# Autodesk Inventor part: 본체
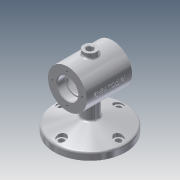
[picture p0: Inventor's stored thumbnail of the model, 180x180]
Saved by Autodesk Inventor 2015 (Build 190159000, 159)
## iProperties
Created: 2018-12
Part Number: 본체
Material: 알루미늄 6061
Document SubType Name: Modeling
Designer: now
Density: 2.7 g/cm^3
Appearance: 알루미늄 - 평지
Mass: 684.769 g
Surface Area: 556.949 cm^2
Volume: 253.618 cm^3
Author: now
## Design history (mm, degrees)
sketch "스케치1"
  geometry: C1 r 30 at (0, 0); 1 further point
  constraints: 1 centre point, 1 coincident
  dimensions: "d0" = 60 diameter of C1
extrude "돌출1" new body sketch "스케치1" stored distance "d1" = 70; taper "d2" = 0 deg
sketch "스케치2"
  geometry: L1 (-35, -30)-(-35, 30) reference; L2 (-35, 30)-(35, 30) reference; L3 (35, 30)-(35, -30) reference; L4 (35, -30)-(-35, -30) reference; L5 (-35, 0)-(-23, 0); L6 (-23, 0)-(-23, 15.7); L7 (-23.3, 16)-(-35, 16); L8 (-35, 16)-(-35, 0); L9 (-23, 0)-(-20, 0); L10 (-20, 0)-(-20, 14); L11 (-20, 14)-(-23, 14); L12 (-23, 14)-(-23, 0); L13 (-20, 0)-(20, 0); L14 (20, 0)-(20, 22); L15 (17, 25)-(-17, 25); L16 (-20, 22)-(-20, 0); L17 (20, 0)-(23, 0); L18 (23, 0)-(23, 14); L19 (23, 14)-(20, 14); L20 (20, 14)-(20, 0); L21 (35, -30)-(35, 30) reference; L22 (23, 0)-(35, 0); L23 (35, 0)-(35, 16); L24 (35, 16)-(23.3, 16); L25 (23, 15.7)-(23, 0); A1 r 3 centre (-17, 22) between (-17, 25) and (-20, 22); A2 r 3 centre (17, 22) between (20, 22) and (17, 25); A3 r 0.3 centre (-23.3, 15.7) between (-23, 15.7) and (-23.3, 16); A4 r 0.3 centre (23.3, 15.7) between (23.3, 16) and (23, 15.7); 1 further point
  constraints: 40 end point, 10 parallel, 8 point on circle, 8 tangent, 5 horizontal, 5 perpendicular, 4 centre point, 2 equal radius, 1 midpoint, 1 point on line
  dimensions: "d3" = 16 distance between parallel lines of L5 L7; "d4" = 12 distance between parallel lines of L1 L6; "d5" = 14 distance between parallel lines of L9 L11; "d6" = 40 distance between parallel lines of L14 L16; "d7" = 25 distance between parallel lines of L13 L15; "d8" = 3 distance between parallel lines of L10 L12; "d9" = 3 distance between parallel lines of L20 L18; "d10" = 14 distance between parallel lines of L19 L17; "d11" = 16 distance between parallel lines of L22 L24; "d12" = 3 radius of A1; "d13" = 0.3 radius of A3
revolve "회전1" sketch "스케치2" stored, may be unused: angle "d14" = 90 deg
chamfer "모따기1" distance "d15" = 1; stored, may be unused: second distance "d16" = 2, angle "d17" = 45 deg
sketch "스케치3" dims "d18" = 46
  geometry: C1 r 30 at (0, 0) reference; C2 r 17 at (0, 0) reference; 2 further points
  constraints: 2 vertical alignment, 1 coincident, 2 other
hole "구멍1" sketch "스케치3" at (0, 23) diameter "d19" = 3.242; stored, may be unused: countersink angle "d23" = 90 deg, drill point angle "d25" = 118 deg; dims "d20" = 8, "d21" = 4, "d22" = 2, "d24" = 10
node "작업 평면1"
sketch "스케치4"
  geometry: C1 r 55 at (0, 0); 1 further point
  constraints: 1 centre point, 1 coincident
  dimensions: "d30" = 110 diameter of C1
extrude "돌출2" join sketch "스케치4" distance "d31" = 11; taper "d32" = 0 deg
sketch "스케치5"
  geometry: C1 r 55 at (0, 0) reference; C2 r 12 at (0, 0)
  constraints: 1 centre point, 1 coincident
  dimensions: "d33" = 24 diameter of C2
extrude "돌출3" join sketch "스케치5" stored distance "d34" = 10; taper "d35" = 0 deg
node "작업 평면2"
sketch "스케치6"
  geometry: C1 r 10 at (0, 0); 1 further point
  constraints: 1 centre point, 1 coincident
  dimensions: "d37" = 20 diameter of C1
extrude "돌출4" join sketch "스케치6" stored distance "d38" = 10; taper "d39" = 0 deg
sketch "스케치7"
  geometry: C1 r 10 at (0, 0) reference; C2 r 5 at (0, 0)
  constraints: 1 centre point, 1 coincident
  dimensions: "d40" = 10 diameter of C2
extrude "돌출5" cut sketch "스케치7" stored distance "d41" = 10; taper "d42" = 0 deg
chamfer "모따기2" distance "d43" = 1; stored, may be unused: second distance "d44" = 2, angle "d45" = 45 deg
fillet "모깎기1" dims "d46" = 3
fillet "모깎기2" dims "d47" = 3
node "작업 평면3"
sketch "스케치8"
  geometry: L1 (-10, 37)-(10, 37) reference; L2 (-35, 30)-(-35, -30) reference; L3 (39.999, -75)-(-39.999, -75) reference; L4 (-39.999, -75)-(-39.999, -64) reference; L5 (-39.999, -64)-(39.999, -64) reference; L6 (39.999, -64)-(39.999, -75) reference; 2 further points
  constraints: 1 other
  dimensions: "d52" = 0 distance of point (0, 0) point (0, 0)
feature "엠보싱1" sketch "스케치8" dims "d3" = 16, "d4" = 12, "d5" = 14, "d6" = 40, "d7" = 25, "d8" = 3, "d9" = 3, "d10" = 14, "d11" = 16, "d12" = 3, "d13" = 0.3, "d53" = 0.5, "d54" = 0
sketch "스케치9"
  geometry: L1 (-23, 14)-(-23, 15.7) reference; L2 (-23.3, 16)-(-34, 16) reference; L3 (-34, 16)-(-35, 17) reference; L4 (-35, 17)-(-35, 21.379) reference; L5 (-35, 21.379)-(-25, 21.379) reference; L6 (-25, 21.379)-(-24.026, 23) reference; L7 (-24.026, 23)-(-25, 24.621) reference; L8 (-25, 24.621)-(-35, 24.621) reference; L9 (-35, 24.621)-(-35, 30) reference; L10 (-35, 30)-(-13, 30) reference; L11 (-10, 33)-(-10, 37) reference; L12 (-10, 37)-(-6, 37) reference; L13 (-6, 37)-(-5, 36) reference; L14 (-5, 36)-(-5, 25) reference; L15 (-5, 25)-(-17, 25) reference; L16 (-20, 22)-(-20, 14) reference; L17 (-20, 14)-(-23, 14) reference; L18 (23, 15.7)-(23, 14) reference; L19 (23, 14)-(20, 14) reference; L20 (20, 14)-(20, 22) reference; L21 (17, 25)-(5, 25) reference; L22 (5, 25)-(5, 36) reference; L23 (5, 36)-(6, 37) reference; L24 (6, 37)-(10, 37) reference; L25 (10, 37)-(10, 33) reference; L26 (13, 30)-(35, 30) reference; L27 (35, 30)-(35, 24.621) reference; L28 (35, 24.621)-(25, 24.621) reference; L29 (25, 24.621)-(24.026, 23) reference; L30 (24.026, 23)-(25, 21.379) reference; L31 (25, 21.379)-(35, 21.379) reference; L32 (35, 21.379)-(35, 17) reference; L33 (35, 17)-(34, 16) reference; L34 (34, 16)-(23.3, 16) reference; L35 (23, -14)-(23, -15.7) reference; L36 (23.3, -16)-(34, -16) reference; L37 (34, -16)-(35, -17) reference; L38 (35, -17)-(35, -21.379) reference; L39 (35, -21.379)-(25, -21.379) reference; L40 (25, -21.379)-(24.026, -23) reference; L41 (24.026, -23)-(25, -24.621) reference; L42 (25, -24.621)-(35, -24.621) reference; L43 (35, -24.621)-(35, -30) reference; L44 (35, -30)-(15, -30) reference; L45 (12, -33)-(12, -64) reference; L46 (12, -64)-(55, -64) reference; L47 (55, -64)-(55, -75) reference; L48 (55, -75)-(-55, -75) reference; L49 (-55, -75)-(-55, -64) reference; L50 (-55, -64)-(-12, -64) reference; L51 (-12, -64)-(-12, -33) reference; L52 (-15, -30)-(-35, -30) reference; L53 (-35, -30)-(-35, -24.621) reference; L54 (-35, -24.621)-(-25, -24.621) reference; L55 (-25, -24.621)-(-24.026, -23) reference; L56 (-24.026, -23)-(-25, -21.379) reference; L57 (-25, -21.379)-(-35, -21.379) reference; L58 (-35, -21.379)-(-35, -17) reference; L59 (-35, -17)-(-34, -16) reference; L60 (-34, -16)-(-23.3, -16) reference; L61 (-23, -15.7)-(-23, -14) reference; L62 (-23, -14)-(-20, -14) reference; L63 (-20, -14)-(-20, -22) reference; L64 (-17, -25)-(17, -25) reference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; A1 r 0.3 centre (-23.3, 15.7) between (-23, 15.7) and (-23.3, 16) reference; A2 r 3 centre (-17, 22) between (-17, 25) and (-20, 22) reference; A3 r 3 centre (17, 22) between (20, 22) and (17, 25) reference; A4 r 0.3 centre (23.3, 15.7) between (23.3, 16) and (23, 15.7) reference; A5 r 0.3 centre (23.3, -15.7) between (23, -15.7) and (23.3, -16) reference; A6 r 0.3 centre (-23.3, -15.7) between (-23.3, -16) and (-23, -15.7) reference; A7 r 3 centre (-17, -22) between (-20, -22) and (-17, -25) reference; A8 r 3 centre (17, -22) between (17, -25) and (20, -22) reference; 1 further point
  constraints: 6 end point, 1 midpoint, 1 vertical, 4 other
  dimensions: "d55" = 75 deg angle of L67 L49
revolve "회전2" sketch "스케치9" stored, may be unused: angle "d56" = 90 deg
fillet "모깎기3" dims "d57" = 3
sketch "스케치10" dims "d58" = 88
  geometry: C1 r 55 at (0, 0) reference; C2 r 4.5 at (-44, 0); 1 further point
  constraints: 1 centre point, 1 coincident, 1 horizontal alignment, 2 other
  dimensions: "d59" = 9 diameter of C2
extrude "돌출6" cut sketch "스케치10" distance "d60" = 10; taper "d61" = 0 deg
sketch "스케치11"
  geometry: C1 r 4.5 at (0, 0) reference; C2 r 7 at (0, 0); 1 further point
  constraints: 1 centre point, 1 coincident
  dimensions: "d62" = 14 diameter of C2
extrude "돌출7" cut sketch "스케치11" distance "d63" = 10; taper "d64" = 0 deg
fillet "모깎기4" dims "d68" = 3
node "솔리드1"
pattern_circular "원형 패턴1" dims angle "d27" = 360 deg
mirror "대칭1"
pattern_circular "원형 패턴2" dims angle "d66" = 360 deg
node "절단 모서리 투영1"
node "절단 모서리 투영2"
node "절단 모서리 투영3"
other parameters: "d29" = -75, "d36" = 37, "d48" = 37.75
